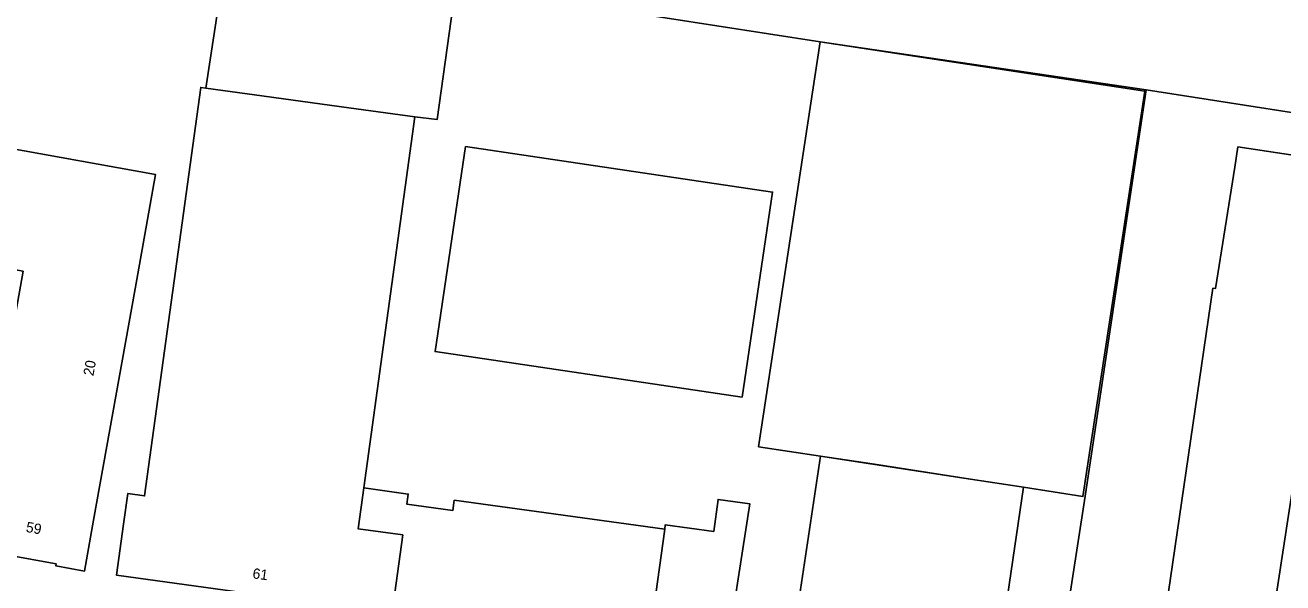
# Model space of a CAD drawing. Extents: x 163008 to 163854, y 382777 to 383982.
# Drawn here: x 163286.5 to 163408.4, y 382871.4 to 382925.4 of the extents above; entities that cross this region are included whole.
import ezdxf

# ---------------------------------------------------------------- set-up
doc = ezdxf.new("R2010")
doc.units = 0
for name, color, linetype in [('IMGEO_Erf', 7, 'Continuous'), ('IMGEO_Open_loods', 7, 'Continuous'), ('IMGEO_Pand', 7, 'Continuous'), ('IMGEO_Pand_nummerreeks', 7, 'Continuous'), ('IMGEO_Pand_vergunning_verleend', 7, 'Continuous'), ('IMGEO_Rijbaan_lokaal_gesloten', 7, 'Continuous')]:
    doc.layers.add(name, color=color, linetype=linetype)

msp = doc.modelspace()

# ---------------------------------------------------------------- linework, layer by layer
at = {"layer": 'IMGEO_Erf'}
for points in [[(163322.05, 382868.43), (163295.36, 382872.1), (163296.04, 382877.06), (163296.45, 382880.01), (163298.08, 382879.78), (163303.53, 382919.38), (163304.01, 382919.31), (163305.62, 382929.89)], [(163328.18, 382928.81), (163326.43, 382916.26), (163324.27, 382916.52), (163319.33, 382880.57), (163323.64, 382879.97), (163323.51, 382878.98), (163327.96, 382878.37), (163328.1, 382879.36), (163348.5, 382876.56), (163348.56, 382877), (163353.25, 382876.35), (163353.68, 382879.45), (163356.75, 382879.03), (163354.66, 382865.53)], [(163386.12, 382859.48), (163389.19, 382879.35), (163395.18, 382919.14), (163363.57, 382923.8), (163338.52, 382927.67)], [(163284.44, 382913.58), (163299.13, 382910.95), (163297.16, 382899.87), (163293.14, 382877.43), (163292.26, 382872.51), (163289.46, 382873.02), (163289.49, 382873.22), (163281.47, 382874.65)], [(163447.25, 382907.1), (163404.08, 382913.62), (163403.77, 382911.64), (163401.9, 382899.88), (163401.65, 382899.91), (163396.25, 382862.98), (163395.49, 382858.04), (163386.39, 382859.44), (163385.73, 382854.85), (163439.9, 382846.82)], [(163360.59, 382863.61), (163363.6, 382883.65), (163378.14, 382881.41), (163383.28, 382880.62), (163380.34, 382860.62)]]:
    msp.add_lwpolyline(points, dxfattribs=at)
for points in [[(163356, 382889.35), (163326.24, 382893.78), (163329.19, 382913.65), (163358.96, 382909.23)], [(163405.76, 382856.82), (163412.34, 382899.86), (163445.44, 382894.88), (163438.86, 382851.75)]]:
    msp.add_lwpolyline(points, close=True, dxfattribs=at)
at = {"layer": 'IMGEO_Open_loods'}
msp.add_lwpolyline([(163405.76, 382856.82), (163438.86, 382851.75), (163445.44, 382894.88), (163412.34, 382899.86)], close=True, dxfattribs=at)
at = {"layer": 'IMGEO_Pand'}
msp.add_lwpolyline([(163409.56, 382977.58), (163388.44, 382980.83), (163388.24, 382979.57), (163376.56, 382981.38), (163376.73, 382982.48), (163332.93, 382989.24), (163330.09, 382970.84), (163335.67, 382969.98), (163334.1, 382959.78), (163339.04, 382959.02), (163367.52, 382954.62), (163366.6, 382948.65), (163346.92, 382951.48), (163346.87, 382951.15), (163337.31, 382952.63), (163333.58, 382928.43), (163338.52, 382927.67), (163363.57, 382923.8), (163395.18, 382919.14), (163418.81, 382915.45)], dxfattribs=at)
for points in [[(163324.27, 382916.52), (163317.18, 382917.5), (163310.37, 382918.44), (163304.01, 382919.31), (163303.53, 382919.38), (163298.08, 382879.78), (163296.45, 382880.01), (163296.04, 382877.06), (163295.36, 382872.1), (163322.05, 382868.43), (163322.27, 382869.99), (163322.33, 382870.41), (163323.1, 382876.01), (163318.78, 382876.6), (163319.33, 382880.57)], [(163419.32, 382918.59), (163418.81, 382915.45), (163395.18, 382919.14), (163389.19, 382879.35), (163386.12, 382859.48), (163386.39, 382859.44), (163395.49, 382858.04), (163396.25, 382862.98), (163401.65, 382899.91), (163401.9, 382899.88), (163403.77, 382911.64), (163404.08, 382913.62), (163447.25, 382907.1), (163448.3, 382914.08), (163438.16, 382915.61)], [(163283.51, 382909.13), (163282.28, 382902.29), (163286.29, 382901.57), (163282.35, 382879.57), (163281.47, 382874.65), (163289.49, 382873.22), (163289.46, 382873.02), (163292.26, 382872.51), (163293.14, 382877.43), (163297.16, 382899.87), (163299.13, 382910.95), (163284.44, 382913.58)], [(163356, 382889.35), (163358.96, 382909.23), (163329.19, 382913.65), (163326.24, 382893.78)], [(163383.28, 382880.62), (163378.14, 382881.41), (163363.6, 382883.65), (163360.59, 382863.61), (163360.91, 382863.57), (163365.38, 382862.89), (163375.46, 382861.36), (163380.34, 382860.62)], [(163348.5, 382876.56), (163328.1, 382879.36), (163327.96, 382878.37), (163323.51, 382878.98), (163323.64, 382879.97), (163319.33, 382880.57), (163318.78, 382876.6), (163323.1, 382876.01), (163322.33, 382870.41), (163326.79, 382869.8), (163326.73, 382869.37), (163331.27, 382868.75), (163331.2, 382868.21), (163331.46, 382868.17), (163331.53, 382868.71), (163346.79, 382866.61), (163346.71, 382866.07), (163347.05, 382866.03), (163347.12, 382866.57)], [(163348.5, 382876.56), (163347.12, 382866.57), (163354.66, 382865.53), (163356.75, 382879.03), (163353.68, 382879.45), (163353.25, 382876.35), (163348.56, 382877)]]:
    msp.add_lwpolyline(points, close=True, dxfattribs=at)
at = {"layer": 'IMGEO_Pand_vergunning_verleend'}
msp.add_lwpolyline([(163357.6, 382884.56), (163363.57, 382923.8), (163395.05, 382919.02), (163389.05, 382879.73), (163383.28, 382880.62), (163378.14, 382881.41), (163368.83, 382882.85), (163363.6, 382883.65)], close=True, dxfattribs=at)
at = {"layer": 'IMGEO_Rijbaan_lokaal_gesloten'}
msp.add_lwpolyline([(163323.33, 383001.14), (163323.2, 383000), (163318.54, 382961.62), (163318.08, 382961.63), (163318.32, 382961.6), (163317.84, 382956.83), (163317.53, 382954.84), (163314.63, 382930.05), (163313.47, 382930.3), (163308.61, 382930.88), (163308.44, 382929.47), (163305.62, 382929.89), (163304.01, 382919.31), (163310.37, 382918.44), (163317.18, 382917.5), (163324.27, 382916.52), (163326.43, 382916.26), (163328.18, 382928.81), (163320.71, 382929.78), (163328.68, 383000.36), (163323.48, 383001.14)], close=True, dxfattribs=at)

# ---------------------------------------------------------------- texts
at = {"layer": 'IMGEO_Pand_nummerreeks'}
for s, rotation, p in [('20', 79.8981, (163293.11, 382891.37)), ('59', 349.8543, (163286.52, 382876.31)), ('61', 352.1677, (163308.5, 382871.81))]:
    msp.add_text(s, height=1, rotation=rotation, dxfattribs=at).set_placement(p)

doc.saveas('drawing.dxf')
